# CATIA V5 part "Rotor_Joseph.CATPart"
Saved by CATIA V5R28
Part number: Open CASCADE STEP translator 7.7 4
Definition: design
Nomenclature: Open CASCADE STEP translator 7.7 4
Source: Unknown
Bounding box of the stored display mesh (mm): x -15.666 to 15.666, y -15.666 to 15.666, z 16.223 to 130.372
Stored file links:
  D:\paraturbo-cad\STEP\Turbocompressor_for_Christophe\Rotor_Joseph.CATPart
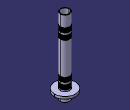
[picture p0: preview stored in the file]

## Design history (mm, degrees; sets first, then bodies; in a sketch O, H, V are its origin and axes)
Body1 "MANIFOLD_SOLID_BREP #15" (main body)
  Solid1: solid without history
